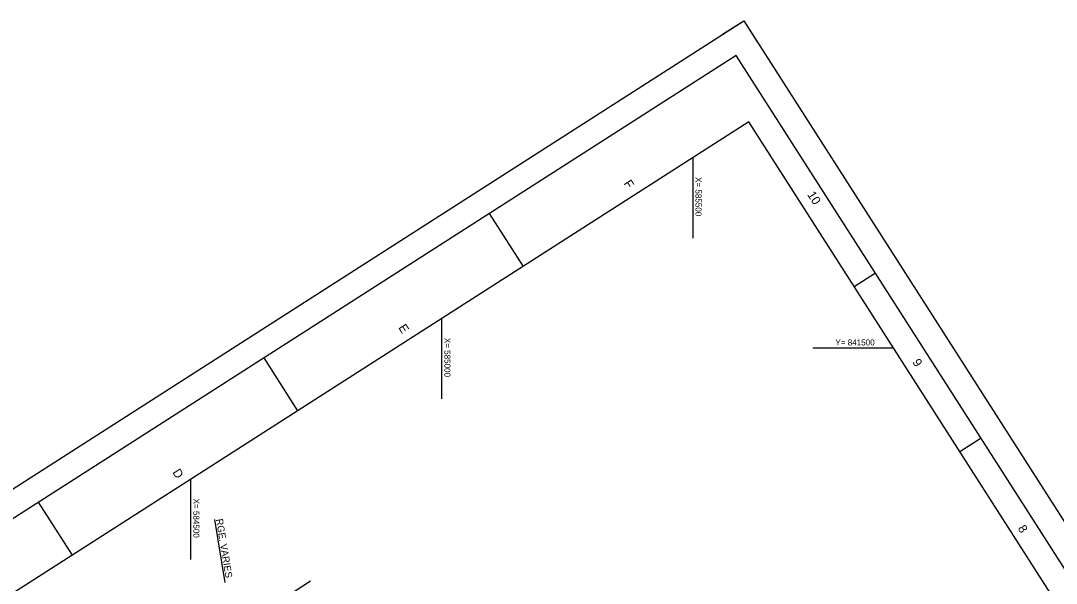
# Model space of a CAD drawing. Extents: x 582737 to 587973, y 836613 to 842151.
# Drawn here: x 584161 to 586223, y 841032 to 842151 of the extents above; entities that cross this region are included whole.
import ezdxf

# ---------------------------------------------------------------- set-up
doc = ezdxf.new("R2010")
doc.units = 0
for name, color, linetype in [('G-ANNO-NPLT', 7, 'Continuous'), ('G-ANNO-TTLB', 7, 'Continuous'), ('V-ALGN-TEXT', 7, 'Continuous'), ('V-ANNO-MATC', 7, 'Continuous'), ('V-TOPO-COOR-STAT', 7, 'Continuous')]:
    doc.layers.add(name, color=color, linetype=linetype)

msp = doc.modelspace()

# ---------------------------------------------------------------- linework, layer by layer
at = {"layer": 'G-ANNO-NPLT'}
msp.add_lwpolyline([(585600.9, 842151.5), (587972.9, 838445.7), (585109.4, 836612.7), (582737.3, 840318.5)], close=True, dxfattribs=at)
msp.add_lwpolyline([(585558.8, 842124.5), (585600.9, 842151.5), (585627.8, 842109.3)], dxfattribs=at)
at = {"layer": 'G-ANNO-TTLB'}
for p, q in [((585094.3, 841767.8), (585161.7, 841662.5)), ((585863.3, 841648.6), (585821.2, 841621.7)), ((584645.1, 841480.3), (584712.5, 841375)), ((586073.6, 841320.2), (586031.5, 841293.2)), ((586073.6, 841320.2), (586031.5, 841293.2)), ((584195.9, 841192.8), (584263.3, 841087.5))]:
    msp.add_line(p, q, dxfattribs=at)
for points in [[(582806.4, 840303.3), (585124.5, 836681.7), (587903.9, 838460.8), (585585.7, 842082.4)], [(587834.8, 838476), (585611, 841950.2), (582915.9, 840225), (585139.7, 836750.8)]]:
    msp.add_lwpolyline(points, close=True, dxfattribs=at)
at = {"layer": 'V-ALGN-TEXT'}
msp.add_line((584547, 841158.7), (584567.9, 841032.8), dxfattribs=at)
at = {"layer": 'V-ANNO-MATC'}
msp.add_line((584738.5, 841035.5), (584228.3, 840708.9), dxfattribs=at)
at = {"layer": 'V-TOPO-COOR-STAT'}
for p, q in [((585500, 841718.8), (585500, 841879.1)), ((585000, 841398.8), (585000, 841559.1)), ((585738.8, 841500), (585899.1, 841500)), ((584500, 841078.7), (584500, 841239))]:
    msp.add_line(p, q, dxfattribs=at)

# ---------------------------------------------------------------- texts
at = {"layer": 'G-ANNO-TTLB'}
for s, p in [('F', (585361.3, 841827.7)), ('10', (585726.9, 841805.2)), ('E', (584912.5, 841540.6)), ('9', (585936.2, 841471.6)), ('D', (584462.7, 841252.5)), ('8', (586146, 841140.8))]:
    msp.add_text(s, height=17.5, rotation=302.6232, dxfattribs=at).set_placement(p)
at = {"layer": 'V-ALGN-TEXT'}
msp.add_text('RGE. VARIES', height=13.92, rotation=279.3882, dxfattribs=at).set_placement((584549.8, 841158.8))
at = {"layer": 'V-TOPO-COOR-STAT'}
for s, p in [('X= 585500', (585504.9, 841840.2)), ('X= 585000', (585004.9, 841520.2)), ('X= 584500', (584504.9, 841200.1))]:
    msp.add_text(s, height=12, rotation=270, dxfattribs=at).set_placement(p)
msp.add_text('Y= 841500', height=12, dxfattribs=at).set_placement((585783.6, 841505))

doc.saveas('drawing.dxf')
